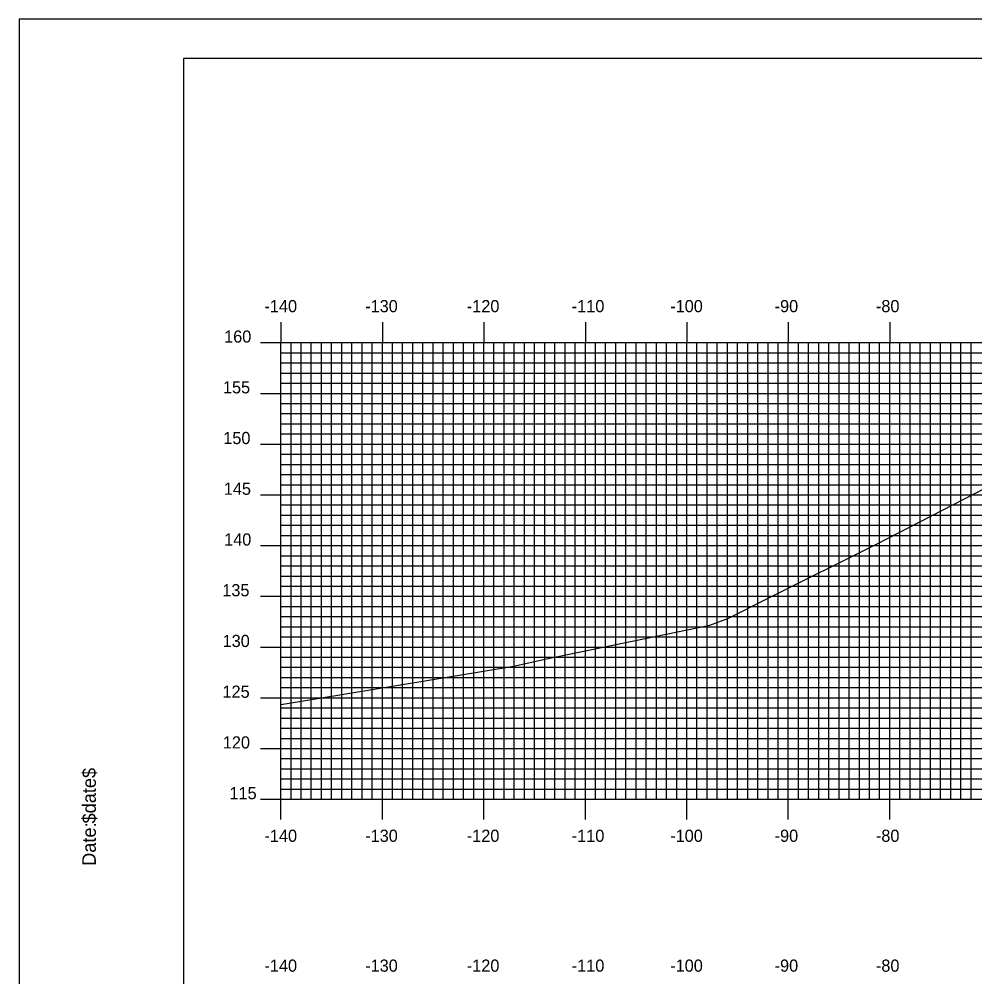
# Model space of a CAD drawing. Extents: x 860652 to 860995, y 364765 to 364985.
# Drawn here: x 860651.6 to 860745.8, y 364890.8 to 364985.2 of the extents above; entities that cross this region are included whole.
import ezdxf

# ---------------------------------------------------------------- set-up
doc = ezdxf.new("R2010")
doc.units = 0
for name, color, linetype in [('BORDER', 7, 'Continuous'), ('H_V ANNOTATION', 7, 'Continuous'), ('MAJOR', 7, 'Continuous'), ('MINOR', 7, 'Continuous'), ('PLOT BOUNDARY', 7, 'Continuous'), ('S_Roadway_Centerline', 7, 'Continuous')]:
    doc.layers.add(name, color=color, linetype=linetype)

msp = doc.modelspace()

# ---------------------------------------------------------------- linework, layer by layer
at = {"layer": 'BORDER'}
msp.add_lwpolyline([(860667.812, 364771.302), (860987.812, 364771.302), (860987.812, 364981.302), (860667.812, 364981.302)], close=True, dxfattribs=at)
at = {"layer": 'MAJOR'}
for p, q in [((860677.412, 364955.306), (860677.412, 364953.302)), ((860687.412, 364955.306), (860687.412, 364953.302)), ((860697.412, 364955.306), (860697.412, 364953.302)), ((860707.412, 364955.306), (860707.412, 364953.302)), ((860717.412, 364955.306), (860717.412, 364953.302)), ((860727.412, 364955.306), (860727.412, 364953.302)), ((860737.412, 364955.306), (860737.412, 364953.302)), ((860675.408, 364953.302), (860677.412, 364953.302)), ((860677.412, 364953.302), (860957.412, 364953.302)), ((860677.412, 364908.302), (860677.412, 364953.302)), ((860677.412, 364908.302), (860677.412, 364953.302)), ((860677.412, 364953.302), (860957.412, 364953.302)), ((860687.412, 364908.302), (860687.412, 364953.302)), ((860697.412, 364908.302), (860697.412, 364953.302)), ((860707.412, 364908.302), (860707.412, 364953.302)), ((860717.412, 364908.302), (860717.412, 364953.302)), ((860727.412, 364908.302), (860727.412, 364953.302)), ((860737.412, 364908.302), (860737.412, 364953.302)), ((860675.408, 364948.302), (860677.412, 364948.302)), ((860677.412, 364948.302), (860957.412, 364948.302)), ((860675.408, 364943.302), (860677.412, 364943.302)), ((860677.412, 364943.302), (860957.412, 364943.302)), ((860675.408, 364938.302), (860677.412, 364938.302)), ((860677.412, 364938.302), (860957.412, 364938.302)), ((860675.408, 364933.302), (860677.412, 364933.302)), ((860677.412, 364933.302), (860957.412, 364933.302)), ((860675.408, 364928.302), (860677.412, 364928.302)), ((860677.412, 364928.302), (860957.412, 364928.302)), ((860675.408, 364923.302), (860677.412, 364923.302)), ((860677.412, 364923.302), (860957.412, 364923.302)), ((860675.408, 364918.302), (860677.412, 364918.302)), ((860677.412, 364918.302), (860957.412, 364918.302)), ((860675.408, 364913.302), (860677.412, 364913.302)), ((860677.412, 364913.302), (860957.412, 364913.302)), ((860675.408, 364908.302), (860677.412, 364908.302)), ((860677.412, 364908.302), (860957.412, 364908.302)), ((860677.412, 364908.302), (860957.412, 364908.302)), ((860677.412, 364906.298), (860677.412, 364908.302)), ((860687.412, 364906.298), (860687.412, 364908.302)), ((860697.412, 364906.298), (860697.412, 364908.302)), ((860707.412, 364906.298), (860707.412, 364908.302)), ((860717.412, 364906.298), (860717.412, 364908.302)), ((860727.412, 364906.298), (860727.412, 364908.302)), ((860737.412, 364906.298), (860737.412, 364908.302))]:
    msp.add_line(p, q, dxfattribs=at)
at = {"layer": 'MINOR'}
for p, q in [((860678.412, 364908.302), (860678.412, 364953.302)), ((860679.412, 364908.302), (860679.412, 364953.302)), ((860680.412, 364908.302), (860680.412, 364953.302)), ((860681.412, 364908.302), (860681.412, 364953.302)), ((860682.412, 364908.302), (860682.412, 364953.302)), ((860683.412, 364908.302), (860683.412, 364953.302)), ((860684.412, 364908.302), (860684.412, 364953.302)), ((860685.412, 364908.302), (860685.412, 364953.302)), ((860686.412, 364908.302), (860686.412, 364953.302)), ((860688.412, 364908.302), (860688.412, 364953.302)), ((860689.412, 364908.302), (860689.412, 364953.302)), ((860690.412, 364908.302), (860690.412, 364953.302)), ((860691.412, 364908.302), (860691.412, 364953.302)), ((860692.412, 364908.302), (860692.412, 364953.302)), ((860693.412, 364908.302), (860693.412, 364953.302)), ((860694.412, 364908.302), (860694.412, 364953.302)), ((860695.412, 364908.302), (860695.412, 364953.302)), ((860696.412, 364908.302), (860696.412, 364953.302)), ((860698.412, 364908.302), (860698.412, 364953.302)), ((860699.412, 364908.302), (860699.412, 364953.302)), ((860700.412, 364908.302), (860700.412, 364953.302)), ((860701.412, 364908.302), (860701.412, 364953.302)), ((860702.412, 364908.302), (860702.412, 364953.302)), ((860703.412, 364908.302), (860703.412, 364953.302)), ((860704.412, 364908.302), (860704.412, 364953.302)), ((860705.412, 364908.302), (860705.412, 364953.302)), ((860706.412, 364908.302), (860706.412, 364953.302)), ((860708.412, 364908.302), (860708.412, 364953.302)), ((860709.412, 364908.302), (860709.412, 364953.302)), ((860710.412, 364908.302), (860710.412, 364953.302)), ((860711.412, 364908.302), (860711.412, 364953.302)), ((860712.412, 364908.302), (860712.412, 364953.302)), ((860713.412, 364908.302), (860713.412, 364953.302)), ((860714.412, 364908.302), (860714.412, 364953.302)), ((860715.412, 364908.302), (860715.412, 364953.302)), ((860716.412, 364908.302), (860716.412, 364953.302)), ((860718.412, 364908.302), (860718.412, 364953.302)), ((860719.412, 364908.302), (860719.412, 364953.302)), ((860720.412, 364908.302), (860720.412, 364953.302)), ((860721.412, 364908.302), (860721.412, 364953.302)), ((860722.412, 364908.302), (860722.412, 364953.302)), ((860723.412, 364908.302), (860723.412, 364953.302)), ((860724.412, 364908.302), (860724.412, 364953.302)), ((860725.412, 364908.302), (860725.412, 364953.302)), ((860726.412, 364908.302), (860726.412, 364953.302)), ((860728.412, 364908.302), (860728.412, 364953.302)), ((860729.412, 364908.302), (860729.412, 364953.302)), ((860730.412, 364908.302), (860730.412, 364953.302)), ((860731.412, 364908.302), (860731.412, 364953.302)), ((860732.412, 364908.302), (860732.412, 364953.302)), ((860733.412, 364908.302), (860733.412, 364953.302)), ((860734.412, 364908.302), (860734.412, 364953.302)), ((860735.412, 364908.302), (860735.412, 364953.302)), ((860736.412, 364908.302), (860736.412, 364953.302)), ((860738.412, 364908.302), (860738.412, 364953.302)), ((860739.412, 364908.302), (860739.412, 364953.302)), ((860740.412, 364908.302), (860740.412, 364953.302)), ((860741.412, 364908.302), (860741.412, 364953.302)), ((860742.412, 364908.302), (860742.412, 364953.302)), ((860743.412, 364908.302), (860743.412, 364953.302)), ((860744.412, 364908.302), (860744.412, 364953.302)), ((860745.412, 364908.302), (860745.412, 364953.302)), ((860677.412, 364952.302), (860957.412, 364952.302)), ((860677.412, 364952.302), (860679.416, 364952.302)), ((860677.412, 364951.302), (860957.412, 364951.302)), ((860677.412, 364951.302), (860679.416, 364951.302)), ((860677.412, 364950.302), (860957.412, 364950.302)), ((860677.412, 364950.302), (860679.416, 364950.302)), ((860677.412, 364949.302), (860957.412, 364949.302)), ((860677.412, 364949.302), (860679.416, 364949.302)), ((860677.412, 364947.302), (860957.412, 364947.302)), ((860677.412, 364947.302), (860679.416, 364947.302)), ((860677.412, 364946.302), (860957.412, 364946.302)), ((860677.412, 364946.302), (860679.416, 364946.302)), ((860677.412, 364945.302), (860957.412, 364945.302)), ((860677.412, 364945.302), (860679.416, 364945.302)), ((860677.412, 364944.302), (860957.412, 364944.302)), ((860677.412, 364944.302), (860679.416, 364944.302)), ((860677.412, 364942.302), (860957.412, 364942.302)), ((860677.412, 364942.302), (860679.416, 364942.302)), ((860677.412, 364941.302), (860957.412, 364941.302)), ((860677.412, 364941.302), (860679.416, 364941.302)), ((860677.412, 364940.302), (860957.412, 364940.302)), ((860677.412, 364940.302), (860679.416, 364940.302)), ((860677.412, 364939.302), (860957.412, 364939.302)), ((860677.412, 364939.302), (860679.416, 364939.302)), ((860677.412, 364937.302), (860957.412, 364937.302)), ((860677.412, 364937.302), (860679.416, 364937.302)), ((860677.412, 364936.302), (860957.412, 364936.302)), ((860677.412, 364936.302), (860679.416, 364936.302)), ((860677.412, 364935.302), (860957.412, 364935.302)), ((860677.412, 364935.302), (860679.416, 364935.302)), ((860677.412, 364934.302), (860957.412, 364934.302)), ((860677.412, 364934.302), (860679.416, 364934.302)), ((860677.412, 364932.302), (860957.412, 364932.302)), ((860677.412, 364932.302), (860679.416, 364932.302)), ((860677.412, 364931.302), (860957.412, 364931.302)), ((860677.412, 364931.302), (860679.416, 364931.302)), ((860677.412, 364930.302), (860957.412, 364930.302)), ((860677.412, 364930.302), (860679.416, 364930.302)), ((860677.412, 364929.302), (860957.412, 364929.302)), ((860677.412, 364929.302), (860679.416, 364929.302)), ((860677.412, 364927.302), (860957.412, 364927.302)), ((860677.412, 364927.302), (860679.416, 364927.302)), ((860677.412, 364926.302), (860957.412, 364926.302)), ((860677.412, 364926.302), (860679.416, 364926.302)), ((860677.412, 364925.302), (860957.412, 364925.302)), ((860677.412, 364925.302), (860679.416, 364925.302)), ((860677.412, 364924.302), (860957.412, 364924.302)), ((860677.412, 364924.302), (860679.416, 364924.302)), ((860677.412, 364922.302), (860957.412, 364922.302)), ((860677.412, 364922.302), (860679.416, 364922.302)), ((860677.412, 364921.302), (860957.412, 364921.302)), ((860677.412, 364921.302), (860679.416, 364921.302)), ((860677.412, 364920.302), (860957.412, 364920.302)), ((860677.412, 364920.302), (860679.416, 364920.302)), ((860677.412, 364919.302), (860957.412, 364919.302)), ((860677.412, 364919.302), (860679.416, 364919.302)), ((860677.412, 364917.302), (860957.412, 364917.302)), ((860677.412, 364917.302), (860679.416, 364917.302)), ((860677.412, 364916.302), (860957.412, 364916.302)), ((860677.412, 364916.302), (860679.416, 364916.302)), ((860677.412, 364915.302), (860957.412, 364915.302)), ((860677.412, 364915.302), (860679.416, 364915.302)), ((860677.412, 364914.302), (860957.412, 364914.302)), ((860677.412, 364914.302), (860679.416, 364914.302)), ((860677.412, 364912.302), (860957.412, 364912.302)), ((860677.412, 364912.302), (860679.416, 364912.302)), ((860677.412, 364911.302), (860957.412, 364911.302)), ((860677.412, 364911.302), (860679.416, 364911.302)), ((860677.412, 364910.302), (860957.412, 364910.302)), ((860677.412, 364910.302), (860679.416, 364910.302)), ((860677.412, 364909.302), (860957.412, 364909.302)), ((860677.412, 364909.302), (860679.416, 364909.302))]:
    msp.add_line(p, q, dxfattribs=at)
at = {"layer": 'PLOT BOUNDARY'}
msp.add_lwpolyline([(860651.626, 364765.184), (860991.626, 364765.184), (860991.626, 364985.184), (860651.626, 364985.184)], close=True, dxfattribs=at)
at = {"layer": 'S_Roadway_Centerline'}
msp.add_lwpolyline([(860677.412, 364917.623), (860678.428, 364917.791), (860700.18, 364921.397), (860700.513, 364921.436), (860703.591, 364922.122), (860719.68, 364925.461), (860721.44, 364926.108), (860725.502, 364928.139), (860736.114, 364933.449), (860751.219, 364941.215)], dxfattribs=at)

# ---------------------------------------------------------------- texts
at = {"layer": 'BORDER'}
for s, p in [('$date$', (860659.182, 364905.912)), ('Date:', (860659.182, 364901.736))]:
    msp.add_text(s, height=1.3392, rotation=90, dxfattribs=at).set_placement(p)
at = {"layer": 'H_V ANNOTATION'}
for s, p in [('-140', (860675.796, 364956.302)), ('-130', (860685.721, 364956.302)), ('-120', (860695.732, 364956.302)), ('-110', (860706.075, 364956.302)), ('-100', (860715.775, 364956.302)), ('-90', (860726.064, 364956.302)), ('-80', (860736.042, 364956.302)), ('160', (860671.822, 364953.302)), ('155', (860671.704, 364948.302)), ('150', (860671.736, 364943.302)), ('145', (860671.79, 364938.302)), ('140', (860671.822, 364933.302)), ('135', (860671.64, 364928.302)), ('130', (860671.672, 364923.302)), ('125', (860671.661, 364918.302)), ('120', (860671.693, 364913.302)), ('115', (860672.347, 364908.302)), ('-140', (860675.796, 364904.102)), ('-130', (860685.721, 364904.102)), ('-120', (860695.732, 364904.102)), ('-110', (860706.075, 364904.102)), ('-100', (860715.775, 364904.102)), ('-90', (860726.064, 364904.102)), ('-80', (860736.042, 364904.102)), ('-140', (860675.796, 364891.302)), ('-130', (860685.721, 364891.302)), ('-120', (860695.732, 364891.302)), ('-110', (860706.075, 364891.302)), ('-100', (860715.775, 364891.302)), ('-90', (860726.064, 364891.302)), ('-80', (860736.042, 364891.302))]:
    msp.add_text(s, height=1.2, dxfattribs=at).set_placement(p)
at = {"layer": 'MAJOR'}
msp.add_text('-', height=0.012, dxfattribs=at).set_placement((860677.403, 364908.302))

doc.saveas('drawing.dxf')
